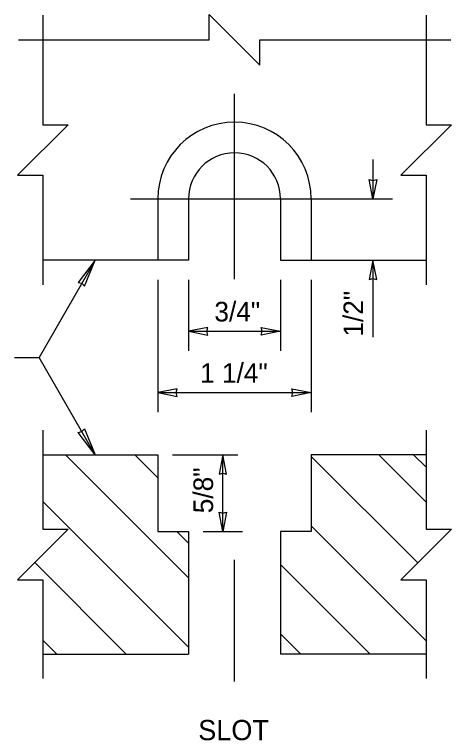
# Model space of a CAD drawing. Extents: x 99862 to 103151, y 100000 to 102076.
# Drawn here: x 102125 to 102481, y 101016 to 101608 of the extents above; entities that cross this region are included whole.
import ezdxf

# ---------------------------------------------------------------- set-up
doc = ezdxf.new("R2010")
doc.units = 0
for name, color, linetype in [('Level 1', 7, 'Continuous'), ('Level 15', 7, 'Continuous'), ('Level 17', 7, 'Continuous'), ('Level 2', 7, 'Continuous'), ('Level 20', 7, 'Continuous')]:
    doc.layers.add(name, color=color, linetype=linetype)

msp = doc.modelspace()

# ---------------------------------------------------------------- linework, layer by layer
at = {"layer": 'Level 15'}
for p, q in [((102304.03, 101391.81), (102304.03, 101542.9)), ((102416.91, 101489.42), (102416.91, 101457.42)), ((102219.3, 101457.42), (102432.91, 101457.42)), ((102190.44, 101407.42), (102144.63, 101328.08)), ((102416.91, 101407.42), (102416.91, 101344.64)), ((102241.53, 101391.42), (102241.53, 101283.42)), ((102266.53, 101391.42), (102266.53, 101333.42)), ((102341.53, 101391.42), (102341.53, 101333.42)), ((102366.53, 101391.42), (102366.53, 101283.42)), ((102266.53, 101349.42), (102341.53, 101349.42)), ((102124.63, 101328.08), (102144.63, 101328.08)), ((102190.44, 101248.75), (102144.63, 101328.08)), ((102241.53, 101299.42), (102366.53, 101299.42)), ((102253.53, 101248.75), (102306.8, 101248.75)), ((102294.53, 101186.25), (102294.53, 101248.75)), ((102278.53, 101186.25), (102310.53, 101186.25)), ((102304.03, 101063.91), (102304.03, 101163.19))]:
    msp.add_line(p, q, dxfattribs=at)
for points in [[(102147.76, 101607.02), (102147.76, 101517.86), (102168.41, 101517.86), (102127.11, 101476.57), (102147.76, 101476.57), (102147.76, 101387.42)], [(102127.76, 101587.02), (102283.38, 101587.02), (102283.38, 101607.66), (102324.67, 101566.37), (102324.67, 101587.02), (102480.29, 101587.02)], [(102460.29, 101607.02), (102460.29, 101517.86), (102480.94, 101517.86), (102439.64, 101476.57), (102460.29, 101476.57), (102460.29, 101387.42)], [(102147.76, 101268.75), (102147.76, 101188.14), (102168.41, 101188.14), (102127.11, 101146.85), (102147.76, 101146.85), (102147.76, 101066.25)], [(102460.29, 101268.75), (102460.29, 101188.14), (102480.94, 101188.14), (102439.64, 101146.85), (102460.29, 101146.85), (102460.29, 101066.25)]]:
    msp.add_lwpolyline(points, dxfattribs=at)
for points in [[(102416.91, 101457.42), (102413.83, 101473.14), (102416.91, 101472.41), (102419.99, 101473.14)], [(102190.44, 101407.42), (102176.44, 101389.14), (102179.55, 101388.56), (102181.61, 101386.15)], [(102416.91, 101407.42), (102413.83, 101391.69), (102416.91, 101392.42), (102419.99, 101391.69)], [(102266.53, 101349.42), (102282.25, 101346.33), (102281.52, 101349.42), (102282.25, 101352.5)], [(102341.53, 101349.42), (102325.8, 101346.33), (102326.53, 101349.42), (102325.8, 101352.5)], [(102241.53, 101299.42), (102257.25, 101296.33), (102256.52, 101299.42), (102257.25, 101302.5)], [(102366.53, 101299.42), (102350.8, 101296.33), (102351.53, 101299.42), (102350.8, 101302.5)], [(102190.44, 101248.75), (102176.44, 101267.02), (102179.55, 101267.6), (102181.61, 101270.01)], [(102294.53, 101248.75), (102291.44, 101233.02), (102294.53, 101233.75), (102297.61, 101233.02)], [(102294.53, 101186.25), (102291.44, 101201.97), (102294.53, 101201.24), (102297.61, 101201.97)]]:
    msp.add_lwpolyline(points, close=True, dxfattribs=at)
at = {"layer": 'Level 17'}
for p, q in [((102266.53, 101148.48), (102166.26, 101248.75)), ((102241.53, 101230.05), (102222.83, 101248.75)), ((102453.38, 101160.58), (102366.53, 101247.43)), ((102460.29, 101210.23), (102421.78, 101248.75)), ((102460.29, 101238.52), (102450.07, 101248.75)), ((102266.53, 101091.91), (102147.76, 101210.68)), ((102266.53, 101176.76), (102257.04, 101186.25)), ((102460.29, 101097.1), (102366.53, 101190.86)), ((102215.62, 101086.25), (102141.07, 101160.8)), ((102414.58, 101086.25), (102341.53, 101159.3)), ((102358.01, 101086.25), (102341.53, 101102.73)), ((102159.05, 101086.25), (102147.76, 101097.54))]:
    msp.add_line(p, q, dxfattribs=at)
at = {"layer": 'Level 2'}
for p, q in [((102241.53, 101457.42), (102241.53, 101407.42)), ((102266.53, 101457.42), (102266.53, 101407.42)), ((102341.53, 101457.42), (102341.53, 101407.42)), ((102366.53, 101457.42), (102366.53, 101407.42)), ((102266.53, 101407.42), (102147.76, 101407.42)), ((102341.53, 101407.42), (102460.29, 101407.42)), ((102147.76, 101248.75), (102241.53, 101248.75)), ((102241.53, 101248.75), (102241.53, 101186.25)), ((102366.53, 101248.75), (102366.53, 101186.25)), ((102460.29, 101248.75), (102366.53, 101248.75)), ((102241.53, 101186.25), (102266.53, 101186.25)), ((102266.53, 101186.25), (102266.53, 101086.25)), ((102366.53, 101186.25), (102341.53, 101186.25)), ((102341.53, 101186.25), (102341.53, 101086.25)), ((102147.76, 101086.25), (102266.53, 101086.25)), ((102460.29, 101086.25), (102341.53, 101086.25))]:
    msp.add_line(p, q, dxfattribs=at)
for radius in [62.5, 37.5]:
    msp.add_arc((102304.03, 101457.42), radius, 360, 180, dxfattribs=at)

# ---------------------------------------------------------------- texts
at = {"layer": 'Level 1'}
msp.add_text('SLOT', height=16.5, dxfattribs=at).set_placement((102274.45, 101016.07))
at = {"layer": 'Level 20'}
for s, p in [('1/2"', (102408.91, 101345.04)), ('5/8"', (102286.53, 101201.07))]:
    msp.add_text(s, height=16, rotation=90, dxfattribs=at).set_placement(p)
for s, p in [('3/4"', (102287.6, 101357.42)), ('1 1/4"', (102275.94, 101307.42))]:
    msp.add_text(s, height=16, dxfattribs=at).set_placement(p)

doc.saveas('drawing.dxf')
